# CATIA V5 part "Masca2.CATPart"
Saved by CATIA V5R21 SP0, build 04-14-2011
Part number: Masca2
Bounding box of the stored display mesh (mm): x 0 to 115, y -115 to 115, z -20 to 20
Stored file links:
  C:\Users\MIRCEA\Desktop\PRRO\CATIAV5\Masca2.CATPart
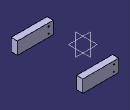
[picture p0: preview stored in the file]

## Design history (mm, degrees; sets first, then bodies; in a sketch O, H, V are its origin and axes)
Body1 (main body)
  Plane1: type Offset, RefPlane zx-plane, Offset -95
  Sketch1 on Plane1, origin (0, -95, 0), H (-1, 0, 0), V (0, 0, 1)
    line L1 (0, 0) -> (0, 20)
    line L2 (0, 0) -> (0, -20)
    line L3 (0, -20) -> (-115, -20)
    line L4 (0, 20) -> (-115, 20)
    line L5 (-115, 20) -> (-115, -20)
    length L1 = 20
    length L2 = 20
    length L3 = 115
    vertical: L1 V, L2 V, L5 V
    horizontal: L3 H, L4 H
  Pad1: profile Sketch1, direction (0, -1, 0), length 20
  Plane2: type Offset, RefPlane Plane1, Offset -20
  Sketch2 on Plane2, origin (0, -115, 0), H (-1, 0, 0), V (0, 0, 1)
    circle A1 centre (-15, 10) radius 2
    circle A2 centre (-15, -10) radius 2
    radius A1 = 2
    radius A2 = 2
  Pocket1: profile Sketch2, direction (0, 1, 0), through (limit type 6)
  Mirror1: of Pad1, Pocket1, about zx-plane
